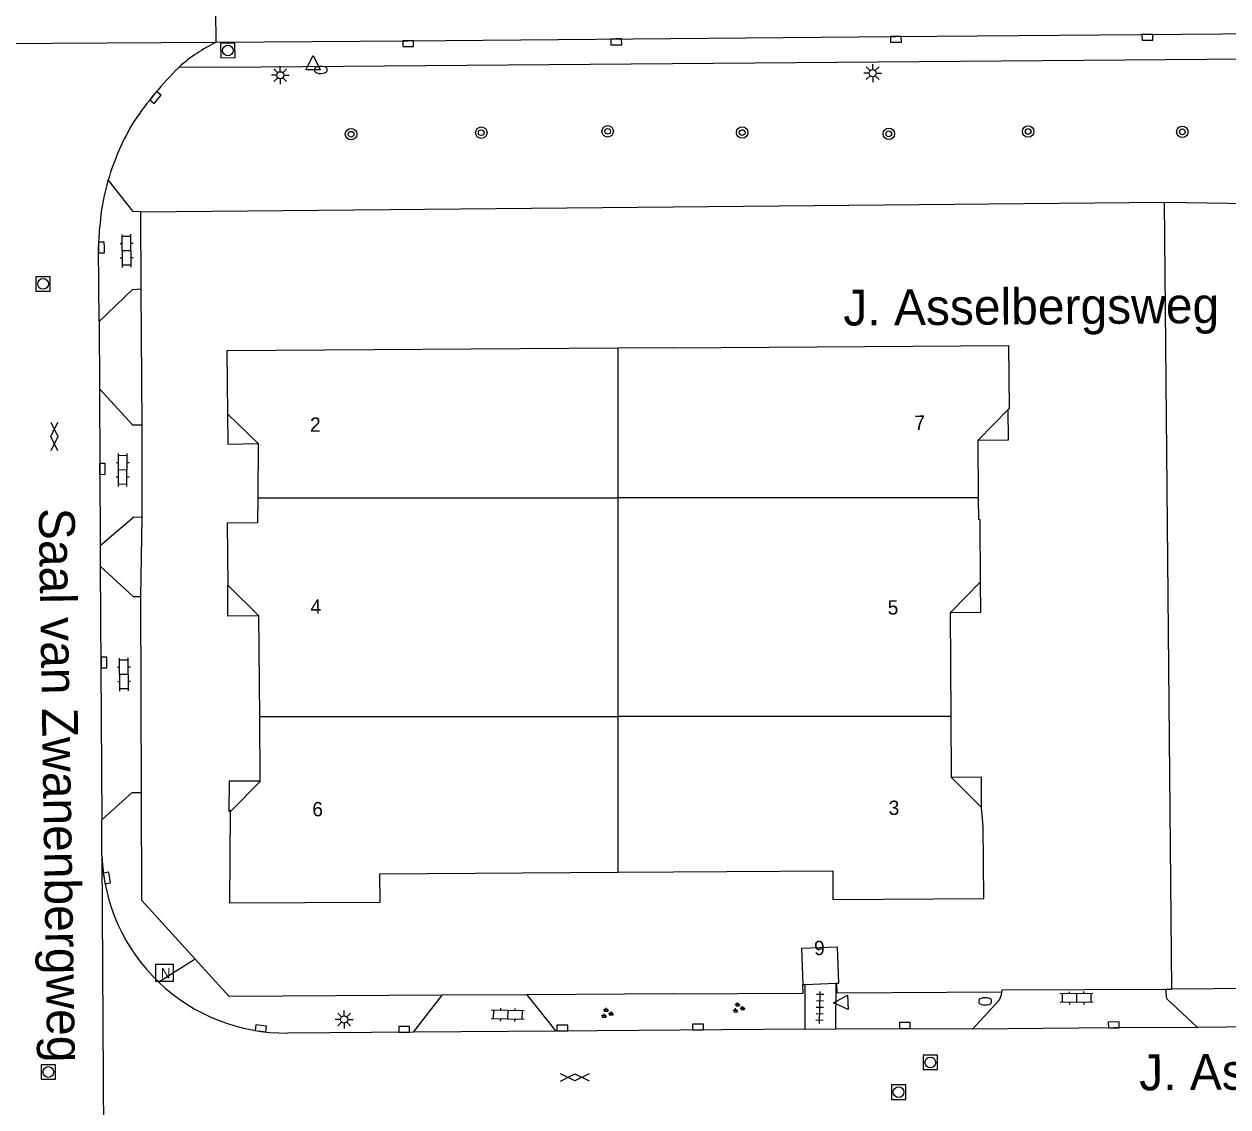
# Model space of a CAD drawing. Extents: x 131000 to 133013, y 393000 to 396501.
# Drawn here: x 131954.7 to 132038.6, y 394909.5 to 394984.9 of the extents above; entities that cross this region are included whole.
import ezdxf

# ---------------------------------------------------------------- set-up
doc = ezdxf.new("R2010")
doc.units = 0
for name, color, linetype in [('gg-afsc-erfafscheiding', 7, 'Continuous'), ('gg-afsc-hekwerk', 7, 'Continuous'), ('gg-anno-huisnummerreeks BGT', 7, 'Continuous'), ('gg-anno-openbare ruimte label', 7, 'Continuous'), ('gg-bbg-hoofdgebouw', 7, 'Continuous'), ('gg-bbg-onder overbouw', 7, 'Continuous'), ('gg-bbg-pand overbouw', 7, 'Continuous'), ('gg-bbg-tussenscheiding', 7, 'Continuous'), ('gg-knt-verharding', 7, 'Continuous'), ('gg-knt-verharding nz', 7, 'Continuous'), ('gt-grn-groengrens', 7, 'Continuous'), ('gt-grn-weggrens', 7, 'Continuous'), ('gt-symb-boom', 7, 'Continuous'), ('gt-symb-brandkraan', 7, 'Continuous'), ('gt-symb-gesloten verharding', 7, 'Continuous'), ('gt-symb-groenvak', 7, 'Continuous'), ('gt-symb-klinker verharding', 7, 'Continuous'), ('gt-symb-kolk', 7, 'Continuous'), ('gt-symb-lichtmast', 7, 'Continuous'), ('gt-symb-nortonput', 7, 'Continuous'), ('gt-symb-rioolschacht', 7, 'Continuous'), ('gt-symb-tegel verharding', 7, 'Continuous'), ('gt-symb-waterafsluiter', 7, 'Continuous')]:
    doc.layers.add(name, color=color, linetype=linetype)

# ---------------------------------------------------------------- blocks, each defined once
blk = doc.blocks.new('gt0-KOLK')
at = {"layer": 'gt-symb-kolk'}
blk.add_lwpolyline([(0, 0), (0.375, 0), (0.375, 0.4), (-0.375, 0.4), (-0.375, 0), (0, 0)], dxfattribs=at)
blk = doc.blocks.new('gt0-BOOM')
at = {"layer": 'gt-symb-boom'}
for radius in [0.4, 0.2]:
    blk.add_circle((0, 0), radius, dxfattribs=at)
blk = doc.blocks.new('gt0-LMAST')
at = {"layer": 'gt-symb-lichtmast'}
for p, q in [((-0.182, 0.173), (-0.447, 0.438)), ((-0.005, 0.246), (-0.005, 0.621)), ((0.172, 0.173), (0.437, 0.438)), ((-0.255, -0.004), (-0.63, -0.004)), ((-0.182, -0.181), (-0.447, -0.446)), ((-0.005, -0.254), (-0.005, -0.629)), ((0.437, -0.446), (0.172, -0.181)), ((0.245, -0.004), (0.62, -0.004))]:
    blk.add_line(p, q, dxfattribs=at)
blk.add_circle((-0.005, -0.004), 0.25, dxfattribs=at)
blk = doc.blocks.new('gt0-RS')
at = {"layer": 'gt-symb-rioolschacht'}
blk.add_lwpolyline([(-0.5, -0.5), (0.5, -0.5), (0.5, 0.5), (-0.5, 0.5)], close=True, dxfattribs=at)
blk.add_circle((0, 0), 0.375, dxfattribs=at)
blk = doc.blocks.new('gt0-WAFSL')
at = {"layer": 'gt-symb-waterafsluiter'}
for p, q in [((-0.5, -0.333), (0, 0.667)), ((0, 0.667), (0.5, -0.333)), ((0.5, -0.333), (-0.5, -0.333))]:
    blk.add_line(p, q, dxfattribs=at)
blk = doc.blocks.new('gt0-BR')
at = {"layer": 'gt-symb-brandkraan'}
for centre, radius, start, end in [((-0.244, 0), 0.206, 107.56694, 252.43307), ((0.599, -2.664), 3, 106.89205, 107.56694), ((0, -0.691), 0.938, 73.10799, 106.89205), ((-0.599, -2.664), 3, 72.43309, 73.10799), ((0.244, 0), 0.206, 287.56695, 72.43309), ((0.599, 2.664), 3, 252.43307, 253.10797), ((0, 0.691), 0.938, 253.10797, 286.89206), ((-0.599, 2.664), 3, 286.89206, 287.56695)]:
    blk.add_arc(centre, radius, start, end, dxfattribs=at)
blk = doc.blocks.new('gt0-KL1')
at = {"layer": 'gt-symb-klinker verharding'}
for p, q in [((-1.15, 0.3), (1.15, 0.3)), ((-1, -0.3), (-1, 0.3)), ((-0.5, 0.3), (-0.5, 0.45)), ((0, -0.3), (0, 0.3)), ((0.5, 0.3), (0.5, 0.45)), ((1, -0.3), (1, 0.3)), ((-1.15, -0.3), (1.15, -0.3)), ((-0.5, -0.45), (-0.5, -0.3)), ((0.5, -0.45), (0.5, -0.3))]:
    blk.add_line(p, q, dxfattribs=at)
blk = doc.blocks.new('gt0-GESVH1')
at = {"layer": 'gt-symb-gesloten verharding'}
for p, q in [((-0.992, -0.261), (0.008, 0.239)), ((0.008, -0.261), (-0.992, 0.239)), ((0.008, 0.239), (1.008, -0.261)), ((1.008, 0.239), (0.008, -0.261))]:
    blk.add_line(p, q, dxfattribs=at)
blk = doc.blocks.new('gt0-TEG1')
at = {"layer": 'gt-symb-tegel verharding'}
for p, q in [((-1.125, 0), (1.125, 0)), ((-0.9, -0.25), (-0.9, 0.25)), ((-0.45, -0.25), (-0.45, 0.25)), ((0, -0.25), (0, 0.25)), ((0.45, -0.25), (0.45, 0.25)), ((0.9, -0.25), (0.9, 0.25))]:
    blk.add_line(p, q, dxfattribs=at)
blk = doc.blocks.new('gt0-GRVAK')
at = {"layer": 'gt-symb-groenvak'}
for p, q in [((-0.11, 0.189), (-0.228, 0.24)), ((-0.182, 0.153), (0.088, 0.153)), ((-0.091, 0.211), (-0.156, 0.322)), ((-0.047, 0.214), (-0.047, 0.393)), ((-0.004, 0.211), (0.061, 0.322)), ((0.015, 0.189), (0.133, 0.24)), ((0.262, -0.052), (0.197, 0.059)), ((0.305, -0.049), (0.305, 0.13)), ((0.349, -0.052), (0.414, 0.059)), ((-0.245, -0.228), (-0.363, -0.177)), ((-0.318, -0.264), (-0.047, -0.264)), ((-0.226, -0.206), (-0.291, -0.095)), ((-0.183, -0.203), (-0.183, -0.024)), ((-0.139, -0.206), (-0.074, -0.095)), ((-0.12, -0.228), (-0.002, -0.177)), ((0.243, -0.074), (0.125, -0.023)), ((0.17, -0.11), (0.441, -0.11)), ((0.368, -0.074), (0.486, -0.023))]:
    blk.add_line(p, q, dxfattribs=at)
blk = doc.blocks.new('gt0-NPUT')
at = {"layer": 'gt-symb-nortonput'}
blk.add_lwpolyline([(-0.566, -0.608), (-0.566, 0.592), (0.634, 0.592), (0.634, -0.608)], close=True, dxfattribs=at)
blk.add_text('N', height=0.7, dxfattribs=at).set_placement((-0.221, -0.381))

msp = doc.modelspace()

# ---------------------------------------------------------------- linework, layer by layer
at = {"layer": 'gg-afsc-erfafscheiding'}
for p, q in [((131962.853, 394971.861), (132000, 394972.21)), ((132000, 394972.21), (132034.217, 394972.532))]:
    msp.add_line(p, q, dxfattribs=at)
at = {"layer": 'gg-afsc-hekwerk'}
for p, q in [((132034.734, 394917.68), (132034.217, 394972.532)), ((131962.946, 394956.982), (131962.886, 394966.482)), ((131962.867, 394945.014), (131962.96, 394950.576)), ((131989.781, 394917.284), (131983.873, 394917.252)), ((132000, 394917.34), (131989.781, 394917.284)), ((132047.078, 394917.793), (132034.734, 394917.68))]:
    msp.add_line(p, q, dxfattribs=at)
for points in [[(131966.661, 394919.765), (131962.94, 394923.852), (131962.904, 394931.389)], [(131983.873, 394917.252), (131969.023, 394917.171), (131966.661, 394919.765)], [(132022.888, 394917.464), (132011.402, 394917.406), (132011.375, 394918.085)], [(132000, 394917.34), (132009.032, 394917.389), (132009.01, 394918)]]:
    msp.add_lwpolyline(points, dxfattribs=at)
at = {"layer": 'gg-bbg-hoofdgebouw'}
for p, q in [((132000, 394962.378), (131996.121, 394962.351)), ((132021.268, 394951.919), (132021.245, 394955.943)), ((131971.035, 394955.695), (131971.01, 394951.918)), ((131971.149, 394936.682), (131971.09, 394943.687)), ((132019.354, 394936.682), (132019.319, 394943.921)), ((131971.188, 394932.141), (131971.149, 394936.682)), ((132019.375, 394932.422), (132019.354, 394936.682)), ((131996.121, 394925.83), (132000, 394925.856)), ((132009.159, 394918.005), (132011.343, 394918.084)), ((132011.343, 394918.084), (132011.375, 394918.085)), ((132009.01, 394918), (132009.159, 394918.005))]:
    msp.add_line(p, q, dxfattribs=at)
for points in [[(132000, 394962.378), (132023.359, 394962.54), (132023.389, 394958.124), (132023.338, 394958.073)], [(131996.121, 394962.351), (131968.864, 394962.161), (131968.908, 394957.782)], [(131971.01, 394951.918), (131970.998, 394950.179), (131968.888, 394950.151), (131968.918, 394945.797)], [(132021.408, 394946.069), (132021.376, 394950.391), (132021.276, 394950.405), (132021.268, 394951.919)], [(131969.102, 394930.041), (131969.034, 394923.681), (131979.538, 394923.739), (131979.517, 394925.721), (131996.121, 394925.83)], [(132000, 394925.856), (132011.097, 394925.931), (132011.101, 394923.933), (132021.621, 394924.005), (132021.586, 394929.005), (132021.475, 394930.326)], [(132011.375, 394918.085), (132011.52, 394918.09), (132011.43, 394920.6), (132008.92, 394920.51), (132009.01, 394918)]]:
    msp.add_lwpolyline(points, dxfattribs=at)
at = {"layer": 'gg-bbg-onder overbouw'}
for p, q in [((131968.908, 394957.782), (131971.035, 394955.695)), ((132021.245, 394955.943), (132023.338, 394958.073)), ((132019.319, 394943.921), (132021.408, 394946.069)), ((132021.475, 394930.326), (132019.375, 394932.422)), ((131971.188, 394932.141), (131969.102, 394930.041))]:
    msp.add_line(p, q, dxfattribs=at)
msp.add_lwpolyline([(131971.09, 394943.687), (131968.986, 394945.782), (131968.986, 394945.728), (131968.918, 394945.797)], dxfattribs=at)
at = {"layer": 'gg-bbg-pand overbouw'}
for points in [[(131968.908, 394957.782), (131968.92, 394955.661), (131971.035, 394955.695)], [(132021.245, 394955.943), (132023.351, 394955.952), (132023.338, 394958.073)], [(131971.09, 394943.687), (131968.924, 394943.67), (131968.918, 394945.797)], [(132019.319, 394943.921), (132021.417, 394943.946), (132021.408, 394946.069)], [(132021.475, 394930.326), (132021.463, 394932.443), (132019.375, 394932.422)], [(131971.188, 394932.141), (131971.058, 394932.143), (131971.089, 394932.174), (131969.012, 394932.183), (131969.003, 394930.057), (131969.101, 394930.156), (131969.102, 394930.041)]]:
    msp.add_lwpolyline(points, dxfattribs=at)
at = {"layer": 'gg-bbg-tussenscheiding'}
for p, q in [((131996.121, 394962.351), (131996.121, 394951.918)), ((131971.01, 394951.918), (131996.121, 394951.918)), ((132021.268, 394951.919), (131996.121, 394951.918)), ((131996.121, 394951.918), (131996.121, 394936.682)), ((131971.149, 394936.682), (131996.121, 394936.682)), ((132019.354, 394936.682), (131996.121, 394936.682)), ((131996.121, 394936.682), (131996.121, 394925.83))]:
    msp.add_line(p, q, dxfattribs=at)
at = {"layer": 'gg-knt-verharding'}
for p, q in [((131960.689, 394973.957), (131960.596, 394974.073)), ((131962.886, 394966.482), (131962.853, 394971.861)), ((131959.948, 394964.196), (131959.973, 394959.508)), ((131959.973, 394959.508), (131960.033, 394948.596)), ((131962.96, 394950.576), (131962.946, 394956.982)), ((131960.033, 394948.596), (131960.04, 394947.15)), ((131960.04, 394947.15), (131960.136, 394929.481)), ((131962.904, 394931.389), (131962.867, 394945.014)), ((131960.15, 394926.954), (131960.136, 394929.481)), ((132011.303, 394914.904), (132011.343, 394918.084)), ((131981.88, 394914.685), (131983.873, 394917.252)), ((131989.781, 394917.284), (131991.79, 394914.759)), ((132009.159, 394918.005), (132009.157, 394914.889)), ((132034.325, 394917.678), (132034.734, 394917.68)), ((131981.88, 394914.685), (131973.1, 394914.62)), ((131991.79, 394914.759), (131981.88, 394914.685)), ((132009.157, 394914.889), (131991.79, 394914.759)), ((132009.157, 394914.889), (132011.303, 394914.904)), ((132020.845, 394914.885), (132011.303, 394914.904)), ((132044.342, 394915.105), (132036.518, 394915.013))]:
    msp.add_line(p, q, dxfattribs=at)
for points in [[(131968.115, 394983.672), (131981.505, 394983.768), (132015.505, 394984.074), (132052.511, 394984.379), (132088.498, 394984.614), (132105.148, 394984.744)], [(132108.847, 394983.044), (131968.395, 394981.918), (131965.529, 394981.931)], [(131960.596, 394974.073), (131960.318, 394972.986), (131960.11, 394971.883), (131959.998, 394970.818)], [(131962.853, 394971.861), (131962.341, 394971.884), (131960.689, 394973.957)], [(131959.948, 394964.196), (131959.92, 394969.34), (131959.998, 394970.818)], [(131959.948, 394964.196), (131962.28, 394966.439), (131962.886, 394966.482)], [(131962.946, 394956.982), (131962.297, 394956.972), (131959.973, 394959.508)], [(131960.033, 394948.596), (131962.378, 394950.594), (131962.96, 394950.576)], [(131962.867, 394945.014), (131962.36, 394945.025), (131960.04, 394947.15)], [(131960.136, 394929.481), (131962.254, 394931.39), (131962.904, 394931.389)], [(132020.845, 394914.885), (132022.713, 394916.941), (132022.861, 394917.275), (132022.888, 394917.464)], [(132022.888, 394917.464), (132022.912, 394917.637), (132034.325, 394917.678)], [(132036.518, 394915.013), (132034.39, 394917.011), (132034.325, 394917.678)], [(132036.518, 394915.013), (132030.686, 394914.987), (132020.845, 394914.885)]]:
    msp.add_lwpolyline(points, dxfattribs=at)
for centre, radius, start, end in [((131972.945, 394973.706), 11.075, 115.85912, 132.04096), ((131984.016, 394963.341), 26.217, 134.84137, 145.59526), ((131977.147, 394969.252), 17.239, 148.9065, 163.76114), ((131972.959, 394927.436), 12.818, 182.1537, 226.32889), ((131972.958, 394927.439), 12.82, 226.34336, 270.63506)]:
    msp.add_arc(centre, radius, start, end, dxfattribs=at)
at = {"layer": 'gg-knt-verharding nz'}
msp.add_line((131945.641, 394983.545), (131968.115, 394983.672), dxfattribs=at)
at = {"layer": 'gt-grn-groengrens'}
msp.add_line((131966.661, 394919.765), (131964.108, 394918.164), dxfattribs=at)
msp.add_lwpolyline([(132034.217, 394972.532), (132053.595, 394972.232), (132093.872, 394972.862), (132110.681, 394972.942)], dxfattribs=at)
at = {"layer": 'gt-grn-weggrens'}
for p, q in [((131968.115, 394983.672), (131968.095, 394985.856)), ((131960.15, 394926.954), (131960.33, 394895.177))]:
    msp.add_line(p, q, dxfattribs=at)

# ---------------------------------------------------------------- block references
at = {"layer": 'gt-symb-boom'}
for p in [(131977.52, 394977.259), (131986.598, 394977.368), (131995.407, 394977.461), (132004.787, 394977.375), (132015.005, 394977.286), (132024.725, 394977.451), (132035.47, 394977.425)]:
    msp.add_blockref('gt0-BOOM', p, dxfattribs=at)
at = {"layer": 'gt-symb-brandkraan', "rotation": -178.6251652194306}
msp.add_blockref('gt0-BR', (131975.414, 394981.741), dxfattribs=at)
at = {"layer": 'gt-symb-brandkraan'}
msp.add_blockref('gt0-BR', (132021.723, 394916.824), dxfattribs=at)
at = {"layer": 'gt-symb-gesloten verharding'}
for p, rotation in [((131956.845, 394956.208), -89.71352348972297), ((131993.11, 394911.54), 0.40106390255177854)]:
    msp.add_blockref('gt0-GESVH1', p, dxfattribs=dict(at, rotation=rotation))
at = {"layer": 'gt-symb-groenvak'}
for p in [(131995.347, 394915.989), (132004.514, 394916.364)]:
    msp.add_blockref('gt0-GRVAK', p, dxfattribs=at)
at = {"layer": 'gt-symb-klinker verharding'}
for p, rotation in [((131961.875, 394969.134), 90.45835645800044), ((131961.607, 394953.856), 89.42706130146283), ((131961.696, 394939.606), 90.45835645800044), ((132028.09, 394917.057), -179.08334574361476), ((131988.434, 394915.89), 178.796965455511)]:
    msp.add_blockref('gt0-KL1', p, dxfattribs=dict(at, rotation=rotation))
at = {"layer": 'gt-symb-kolk'}
for p, rotation in [((131981.505, 394983.768), -179.59893609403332), ((131996.007, 394983.897), -179.4843519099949), ((132015.505, 394984.074), -179.48435190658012), ((132033.03, 394984.215), -179.54164354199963), ((131963.728, 394979.947), -129.27731149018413), ((131960.32, 394969.369), 90.34377055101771), ((131960.384, 394953.932), 90.34377055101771), ((131960.495, 394940.442), 90.3437705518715), ((131960.302, 394925.383), -80.20785375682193), ((131971.207, 394914.745), -7.8141808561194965), ((132030.686, 394914.987), 0.22918189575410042)]:
    msp.add_blockref('gt0-KOLK', p, dxfattribs=dict(at, rotation=rotation))
for p in [(131981.218, 394914.681), (131992.247, 394914.763), (132001.707, 394914.833), (132016.127, 394914.944)]:
    msp.add_blockref('gt0-KOLK', p, dxfattribs=at)
at = {"layer": 'gt-symb-lichtmast'}
for p in [(131972.592, 394981.371), (132013.887, 394981.517), (131977.041, 394915.563)]:
    msp.add_blockref('gt0-LMAST', p, dxfattribs=at)
at = {"layer": 'gt-symb-nortonput'}
msp.add_blockref('gt0-NPUT', (131964.473, 394918.821), dxfattribs=at)
at = {"layer": 'gt-symb-rioolschacht', "rotation": -177.99346106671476}
msp.add_blockref('gt0-RS', (131968.929, 394983.096), dxfattribs=at)
at = {"layer": 'gt-symb-rioolschacht'}
for p in [(131956.049, 394966.829), (132017.902, 394912.568), (131956.414, 394911.903), (132015.688, 394910.497)]:
    msp.add_blockref('gt0-RS', p, dxfattribs=at)
at = {"layer": 'gt-symb-tegel verharding', "rotation": 88.56790381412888}
msp.add_blockref('gt0-TEG1', (132010.194, 394916.399), dxfattribs=at)
at = {"layer": 'gt-symb-waterafsluiter'}
msp.add_blockref('gt0-WAFSL', (131974.874, 394982.081), dxfattribs=at)
at = {"layer": 'gt-symb-waterafsluiter', "rotation": 92.06381972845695}
msp.add_blockref('gt0-WAFSL', (132011.818, 394916.75), dxfattribs=at)

# ---------------------------------------------------------------- texts
at = {"layer": 'gg-anno-huisnummerreeks BGT'}
for s, rotation, p in [('2', 359.6, (131974.653, 394956.524)), ('7', 0.9, (132016.801, 394956.65)), ('4', 0.5, (131974.696, 394943.833)), ('5', 0.3, (132014.931, 394943.779)), ('6', 0.5, (131974.821, 394929.719)), ('3', 0.3, (132014.999, 394929.814)), ('9', 2.1, (132009.814, 394920.033))]:
    msp.add_text(s, height=1, rotation=rotation, dxfattribs=at).set_placement(p)
at = {"layer": 'gg-anno-openbare ruimte label'}
for s, rotation, p in [('J. Asselbergsweg', 0.4, (132011.843, 394963.919)), ('Saal van Zwanenbergweg', 270.9, (131955.746, 394951.204)), ('J. Asselbergsweg', 0.4, (132032.469, 394910.622))]:
    msp.add_text(s, height=2.5, rotation=rotation, dxfattribs=at).set_placement(p)

doc.saveas('drawing.dxf')
